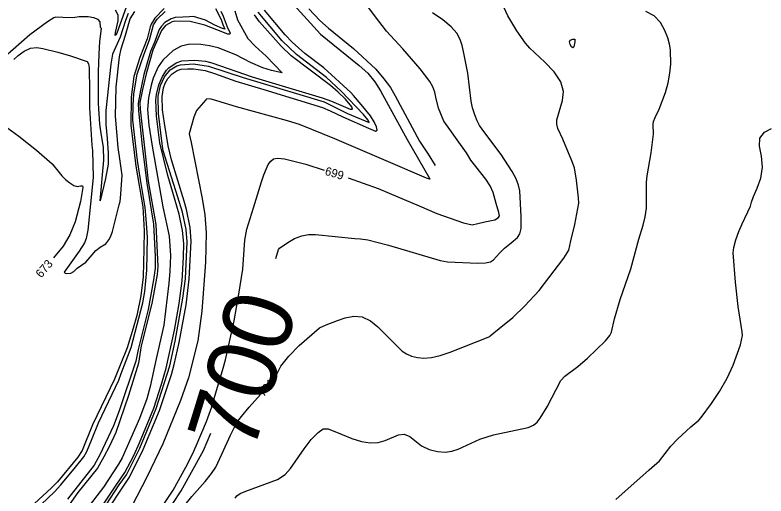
# Model space of a CAD drawing. Extents: x -291892836 to 2945206, y -477993085 to 1832792.
# Drawn here: x 1852014.8 to 1852371.2, y 544783.9 to 545011.9 of the extents above; entities that cross this region are included whole.
import ezdxf

# ---------------------------------------------------------------- set-up
doc = ezdxf.new("R2010")
doc.units = 0
for name, color, linetype in [('DT_X_Contour_Minor', 7, 'Continuous'), ('DT_X_Terrain_Ground_Line', 7, 'Continuous'), ('Level 19', 7, 'Continuous')]:
    doc.layers.add(name, color=color, linetype=linetype)

msp = doc.modelspace()

# ---------------------------------------------------------------- linework, layer by layer
at = {"layer": 'DT_X_Contour_Minor'}
for points in [[(1852214.38, 544973.71), (1852214.04, 544975.4), (1852213.18, 544977.82), (1852211.65, 544980.48), (1852207.06, 544986.4), (1852198.88, 544995.84), (1852191.2, 545004.25), (1852185.5, 545011.67), (1852172, 545029.89), (1852170.75, 545032.2)], [(1852147.09, 545016.73), (1852159.78, 545002.93), (1852178.21, 544988.01), (1852182.22, 544984.33), (1852185.62, 544980.29), (1852188.33, 544975.96), (1852200.96, 544952.88), (1852211.73, 544934.29), (1852211.57, 544934.15), (1852210.07, 544934.63), (1852190.98, 544942.85), (1852166.68, 544953.26), (1852149.87, 544960), (1852144.07, 544961.7), (1852120, 544968.37), (1852110.56, 544971.18), (1852107.98, 544972.05), (1852105.9, 544972.21), (1852105.34, 544971.8), (1852101.02, 544966.62), (1852099.68, 544963.48), (1852097.51, 544955.6), (1852098.34, 544951.54), (1852103.61, 544924.88), (1852104.86, 544917.24), (1852105.54, 544908.68), (1852105.23, 544894.74), (1852103.54, 544871.46), (1852101.51, 544857.41), (1852097.2, 544839.91)], [(1852138.97, 544841.34), (1852140.92, 544845.38), (1852144.72, 544850.23), (1852149.71, 544855.27), (1852159.38, 544863.65), (1852162.54, 544865.12), (1852167.91, 544867.17), (1852171.54, 544868.39), (1852175.56, 544869.15), (1852179.65, 544868.79), (1852183.52, 544866.89), (1852187, 544864.06), (1852198.64, 544852.48), (1852200.62, 544851.22), (1852203, 544850.19), (1852205.77, 544849.49), (1852208.92, 544849.26), (1852212.47, 544849.6), (1852216.54, 544850.53), (1852221.33, 544852.08), (1852240.15, 544859.5), (1852240.35, 544859.86), (1852244.62, 544863.23), (1852251.08, 544868.55), (1852256.86, 544874.12), (1852263.51, 544881.38), (1852275.27, 544896.6), (1852277.62, 544900.39), (1852278.69, 544904.85), (1852280.45, 544912.54), (1852282.4, 544922.67), (1852282.33, 544925.3), (1852281.32, 544933.58), (1852280.33, 544939.46), (1852279.13, 544942.8), (1852274.76, 544953.04), (1852272.37, 544958.13), (1852271.9, 544960.15), (1852272.05, 544962.26), (1852274.73, 544971.36), (1852275.06, 544975.63), (1852273.85, 544980.27), (1852270.64, 544985.05), (1852266.32, 544989.57), (1852259.21, 544996.27), (1852257.06, 544998.66), (1852252.93, 545004.41), (1852248.74, 545011.5), (1852245.08, 545019.58)], [(1852020.98, 544773.99), (1852033.57, 544785.79), (1852036.54, 544789.14), (1852043.52, 544797.62), (1852047.42, 544802.51), (1852048.86, 544805), (1852051.15, 544810.43), (1852054.44, 544818.5), (1852064.02, 544838.79), (1852065.22, 544842.02), (1852069.92, 544854.34), (1852075.54, 544875.49), (1852076.42, 544880.9), (1852077.39, 544891.01), (1852077.66, 544906.44), (1852077.28, 544913.23), (1852076.59, 544920.72), (1852074.29, 544933.94), (1852072.87, 544942.97), (1852070.77, 544962.04), (1852070.83, 544969.26), (1852071.19, 544974.61), (1852072.81, 544983.89), (1852075.93, 544993.01), (1852078.64, 545000.18), (1852080.53, 545007.31), (1852082.26, 545009.92), (1852086, 545013.61)], [(1852112.42, 545013.84), (1852113.55, 545011.34), (1852115.44, 545006.29), (1852116.91, 545003.38), (1852116.73, 545002.84), (1852115.77, 545002.91), (1852110.56, 545004.94), (1852104.92, 545007.19), (1852097.96, 545008.94), (1852090.44, 545008.96), (1852089.47, 545008.75), (1852086.16, 545006.98), (1852084.3, 545004.67), (1852080.25, 544995.24), (1852077.02, 544984.01), (1852075.33, 544976.68), (1852074.08, 544970.43), (1852074.22, 544967.33), (1852077, 544941.86), (1852078.08, 544933.09), (1852081.71, 544912.65), (1852082.67, 544892.63), (1852082.28, 544888.89), (1852079.7, 544875.23), (1852074.68, 544855.01), (1852073.39, 544846.85), (1852068.64, 544831.61), (1852062.71, 544814.04), (1852059.62, 544807.45), (1852056.93, 544802.52), (1852053.99, 544797.13), (1852044.69, 544785.58), (1852037.55, 544775.43)], [(1852049.4, 544909.93), (1852048.54, 544905.97), (1852047.74, 544903.95), (1852045.23, 544899.94), (1852038.19, 544890.05), (1852038.63, 544889.56), (1852039.47, 544889.33), (1852041.38, 544889.57), (1852042.74, 544890.36), (1852044.32, 544891.86), (1852048.35, 544894.79), (1852050.51, 544897.18), (1852053.13, 544900.3), (1852055.17, 544901.81), (1852057.93, 544903.42), (1852059.38, 544905.36), (1852060.26, 544907.06), (1852061.09, 544909.35), (1852064.31, 544921.86), (1852064.78, 544923.46), (1852065.08, 544927.06), (1852065.61, 544935.94), (1852064.68, 544942.59), (1852063.71, 544949.11), (1852062.49, 544963.99), (1852062.81, 544977.73), (1852064.44, 544992.11), (1852065.2, 544995.89), (1852067.29, 545002.32), (1852069.44, 545010.14), (1852071.64, 545013.68)], [(1852109.97, 545014.98), (1852112.59, 545009.84), (1852113.48, 545007.51), (1852114.4, 545005.21), (1852113.3, 545005.47), (1852109.67, 545007.11), (1852105.17, 545009.44), (1852099.57, 545011.28), (1852097.66, 545011.01), (1852094.47, 545010.91), (1852090.82, 545010.76), (1852088.99, 545010.18), (1852085.95, 545008.46), (1852084.28, 545006.64), (1852083.22, 545005.02), (1852082.07, 545002.02), (1852081.13, 544999.4), (1852079.17, 544994.68), (1852075.9, 544983.74), (1852074.3, 544976.17), (1852073.27, 544970.14), (1852073.35, 544966.47), (1852075.12, 544949.73), (1852077.33, 544932.18), (1852080.6, 544912.79), (1852081.34, 544897.45), (1852081.33, 544891.9), (1852080.6, 544886.44), (1852077.95, 544872.33), (1852073.29, 544853.41), (1852072.13, 544847.85), (1852064.23, 544824.25), (1852061.54, 544817.08), (1852055.06, 544803.45), (1852052.35, 544798.48), (1852039.8, 544782.37)], [(1852119.1, 545013.89), (1852120.48, 545009.71), (1852125.25, 545000.87), (1852128.73, 544997.14), (1852134.07, 544992.39), (1852141.6, 544984.47), (1852136.53, 544985.63), (1852132.37, 544986.95), (1852126.52, 544989.49), (1852119.57, 544993.05), (1852111.26, 544996.37), (1852107.11, 544997.4), (1852102.99, 544997.98), (1852097.73, 544998.07), (1852093.62, 544997.2), (1852089.88, 544995.16), (1852084.91, 544990.59), (1852082.82, 544987.35), (1852080.38, 544982.02), (1852079.51, 544978.69), (1852078.16, 544972.61), (1852077.68, 544967.1), (1852078.36, 544959.78), (1852079.85, 544949.79), (1852084.93, 544921.03), (1852087.97, 544907.04), (1852088.53, 544897.94), (1852088.37, 544890.4), (1852087.81, 544884.76), (1852085.46, 544864.93), (1852081.87, 544848.92), (1852079.02, 544835.76), (1852077.36, 544829.92), (1852073.95, 544820.65), (1852065.69, 544802.01), (1852063.87, 544799), (1852056.74, 544788.06), (1852048.44, 544777.17)], [(1852053.89, 544773.45), (1852064.29, 544789.15), (1852067.7, 544793.96), (1852074.03, 544806.57), (1852081.83, 544825.31), (1852088.3, 544845.57), (1852090.89, 544857.31), (1852094.53, 544877.67), (1852095.7, 544886.89), (1852096.59, 544904.39), (1852095.99, 544910.3), (1852094.33, 544918.5), (1852092.09, 544925.64), (1852085.2, 544947.52), (1852084.66, 544950.85), (1852082.99, 544965.26), (1852082.82, 544973.46), (1852083.87, 544978.51), (1852085.81, 544982.62), (1852088.48, 544986), (1852091.58, 544987.84), (1852093.3, 544988.38), (1852099.51, 544988.72), (1852106.63, 544987.75), (1852123.06, 544982.31), (1852148.45, 544974.69), (1852161.56, 544970.71), (1852172.62, 544965.19), (1852182.98, 544961.05), (1852182.48, 544962.15), (1852180.27, 544964.78), (1852169.65, 544975.88), (1852162.7, 544982.36), (1852148.39, 544993.19), (1852141.6, 544999.77), (1852130.21, 545013.29)], [(1852055.73, 544772.58), (1852069.07, 544792.88), (1852075.58, 544805.9), (1852083.38, 544824.45), (1852089.1, 544841.51), (1852090.39, 544846.22), (1852092.75, 544856.72), (1852096.05, 544874.54), (1852097.44, 544886.66), (1852098.37, 544904.76), (1852097.91, 544911.25), (1852096.14, 544919.72), (1852095.06, 544923.67), (1852089.15, 544943.31), (1852087.49, 544949.91), (1852085.79, 544960.65), (1852084.88, 544967.06), (1852084.66, 544973.28), (1852085.32, 544977.45), (1852086.12, 544979.59), (1852087.42, 544981.76), (1852089.36, 544984.08), (1852091.78, 544985.6), (1852093.64, 544986.26), (1852096.86, 544986.49), (1852099.5, 544986.44), (1852105.11, 544985.64), (1852109.52, 544984.25), (1852117.4, 544981.36), (1852119.6, 544980.62), (1852132.86, 544976.67), (1852160.75, 544968.11), (1852164.39, 544966.51), (1852170.38, 544963.6), (1852182.55, 544958.33), (1852185.98, 544956.87), (1852186.66, 544957.27), (1852186.38, 544958.85), (1852185.26, 544961.3), (1852183.5, 544964.15), (1852179.12, 544969.48), (1852175.43, 544973.8), (1852174.23, 544975.21), (1852161.33, 544986.87), (1852152.32, 544993.76), (1852146.3, 544999.07), (1852143.03, 545002.56), (1852133.23, 545014.2)], [(1852067.54, 545015.59), (1852063.2, 545003.32), (1852062.32, 545002.22), (1852062.45, 545003.57), (1852063.76, 545009.18), (1852063.8, 545011.82), (1852062.47, 545014.25)], [(1852085.62, 545015.07), (1852081.13, 545010.46), (1852079.39, 545007.62), (1852079, 545006.26), (1852077.59, 545000.66), (1852074.09, 544991.87), (1852071.2, 544982.76), (1852069.87, 544972.93), (1852069.76, 544959.77), (1852072.09, 544940.32), (1852075.4, 544921.04), (1852076.17, 544909.64), (1852076.03, 544901.13)], [(1852138.67, 544896.46), (1852139.82, 544900.74), (1852140.41, 544901.38), (1852144.3, 544904.14), (1852147.49, 544905.91), (1852150.89, 544907.31), (1852154.13, 544907.93), (1852157.39, 544907.9), (1852176.02, 544905.92), (1852178.83, 544905.84), (1852182.32, 544905.38), (1852192.02, 544902.88), (1852216.67, 544895.57), (1852220.14, 544894.93), (1852234.51, 544894.29), (1852238.04, 544894.41), (1852240.45, 544894.96), (1852241.95, 544895.85), (1852244.69, 544899.03), (1852247.09, 544901.47), (1852250.29, 544903.98), (1852253.38, 544906.38), (1852254.45, 544908.19), (1852254.99, 544910.74), (1852255.06, 544916.43), (1852254.37, 544928.6), (1852253.74, 544931.21), (1852252.6, 544934.22), (1852250.81, 544937.72), (1852245.5, 544945.81), (1852237.76, 544956.03), (1852235.31, 544959.54), (1852234.14, 544961.81), (1852232.99, 544964.66), (1852231.98, 544967.86), (1852231.26, 544971.12), (1852229.7, 544984.29), (1852227.61, 544994.7), (1852227.07, 544997.53), (1852226.13, 545000.32), (1852224.45, 545003.28), (1852221.78, 545006.41), (1852217.94, 545009.66), (1852212.95, 545012.91)], [(1852154.32, 545014.87), (1852159.49, 545009.38), (1852163.6, 545005.69), (1852175.41, 544996.08), (1852186.05, 544986.29), (1852189.91, 544981.71), (1852193.02, 544977.57), (1852195.22, 544973.69), (1852206.81, 544952.11), (1852210.93, 544945.93), (1852214.26, 544940.59)], [(1852314.6, 544932.69), (1852314.9, 544935.7), (1852316.81, 544946.58), (1852317.79, 544955.5), (1852317.74, 544960.05), (1852317.89, 544961.44), (1852318.72, 544963.29), (1852320.6, 544967.24), (1852323.57, 544975.13), (1852324.86, 544979.82), (1852325.67, 544984.44), (1852326.05, 544988.7), (1852325.95, 544995.41), (1852325.5, 544998.15), (1852324.66, 545001.13), (1852323.31, 545004.66), (1852321.24, 545008.33), (1852318.22, 545011.48), (1852314.18, 545013.62)], [(1852057.88, 544966.66), (1852057.84, 544960.09), (1852058.47, 544953.45), (1852059, 544946.39), (1852059, 544941.25), (1852057.73, 544934.5), (1852055.16, 544923.78), (1852056.96, 544943.05), (1852056.78, 544949.24), (1852055.67, 544955.83), (1852055.12, 544960.22), (1852054.47, 544969.98), (1852054.46, 544985.07), (1852054.77, 544993.36), (1852055.07, 544999.33), (1852055.8, 545005.53), (1852055.39, 545006.05), (1852055.24, 545008.73), (1852054.25, 545009.78), (1852052.15, 545010.57), (1852049.48, 545011.05), (1852045.23, 545011.1), (1852042.21, 545010.65), (1852037.52, 545010.76), (1852034.15, 545010.93), (1852033.23, 545010.68), (1852030.27, 545008.74), (1852021.9, 545002.57), (1852001.84, 544985.23)], [(1852055.79, 544778.67), (1852062.79, 544789.05), (1852066.95, 544794.96), (1852071.17, 544803.13), (1852073.88, 544809.04), (1852080.74, 544825.58), (1852084.37, 544836.95), (1852086.63, 544844.48), (1852090.51, 544862.48), (1852092.74, 544875.13), (1852094.07, 544885.9), (1852094.76, 544897.06), (1852094.94, 544903.57), (1852094.36, 544909.76), (1852092.76, 544917.52), (1852090.54, 544925.12), (1852087.34, 544935.91), (1852083.53, 544951.38), (1852082.01, 544964), (1852081.71, 544971.71), (1852082.04, 544974.28), (1852083.08, 544978.87), (1852084.75, 544982.81), (1852086.7, 544985.71), (1852087.79, 544986.95), (1852091.3, 544989.34), (1852093.92, 544990.15), (1852100.13, 544990.59), (1852105.25, 544989.98), (1852108.27, 544989.21), (1852127.3, 544982.62), (1852146.39, 544976.98), (1852160.67, 544972.71), (1852164.97, 544971.15), (1852173.96, 544967.27), (1852175.04, 544967.34), (1852174.75, 544968.36), (1852171.67, 544971.96), (1852168.19, 544975.4), (1852164.5, 544978.46), (1852145.88, 544992.59), (1852141.07, 544997.22), (1852130.85, 545008.71), (1852128.53, 545011.99)], [(1852068.48, 545012.58), (1852067.28, 545009.26), (1852064.77, 545001.4), (1852061.01, 544993.45), (1852060.28, 544988.65), (1852057.88, 544966.66)], [(1852280.49, 545000.48), (1852280.46, 544999.17), (1852280.07, 544996.88), (1852279.61, 544996.37), (1852278.95, 544996.88), (1852278.33, 544998.01), (1852278.05, 544999.19), (1852278.33, 544999.95), (1852279.6, 545000.47), (1852280.49, 545000.48)], [(1852014.18, 544990.81), (1852016.35, 544992.72), (1852019.11, 544994.77), (1852022.14, 544996.21), (1852025.16, 544996.52), (1852028.02, 544996.05), (1852035.09, 544994.25), (1852041.08, 544992.62), (1852049, 544989.84), (1852049.76, 544988.83), (1852050.01, 544986.84), (1852050.11, 544975.76), (1852050.24, 544967.86), (1852051.29, 544950.26), (1852051.57, 544947.64), (1852051.84, 544934.86), (1852049.4, 544909.93)], [(1852221.13, 544957.73), (1852218.28, 544961.68), (1852215.87, 544967.72), (1852214.52, 544973.03), (1852214.38, 544973.71)], [(1852009.7, 544959.5), (1852016.68, 544954.46), (1852025.02, 544947.86), (1852032.46, 544941.33), (1852035.78, 544937.26), (1852037.04, 544935.64), (1852038.81, 544933.91), (1852040.87, 544932.3), (1852042.8, 544931.15), (1852044.25, 544930.68), (1852045.95, 544930.91), (1852046.87, 544930.94), (1852046.98, 544930.17), (1852045.89, 544923.45), (1852043.39, 544913.95), (1852040.87, 544907.77), (1852037.73, 544902.36), (1852033.02, 544896.85)], [(1852206.59, 544921.44), (1852215.04, 544917.84), (1852227.6, 544913.46), (1852231.77, 544912.5), (1852234.54, 544913.08), (1852237.86, 544913.91), (1852242.54, 544914.76), (1852244.33, 544916), (1852244.69, 544916.71), (1852244.48, 544918.36), (1852243.14, 544922.53), (1852241.81, 544927.74), (1852240.4, 544930.88), (1852238.2, 544934.15), (1852231.15, 544943.08), (1852229.14, 544946.59), (1852224.73, 544952.73), (1852221.13, 544957.73)], [(1852299.94, 544782.28), (1852315.86, 544796.37), (1852320.66, 544800.51), (1852326.12, 544807.44), (1852329.18, 544810.83), (1852335.57, 544816.64), (1852339.39, 544819.79), (1852340.54, 544821.08), (1852345.41, 544827.79), (1852349.19, 544833.47), (1852352.87, 544839.75), (1852355.74, 544845.91), (1852359.09, 544855.51), (1852360.17, 544859.92), (1852359.94, 544861.72), (1852358.04, 544873.74), (1852356.81, 544885.22), (1852355.64, 544899.2), (1852355.94, 544901.78), (1852356.88, 544905.29), (1852358.28, 544909.27), (1852359.86, 544912.98), (1852363.95, 544921.26), (1852364.39, 544923.14), (1852365.31, 544925.87), (1852367, 544929.81), (1852368.74, 544934.64), (1852369.63, 544939.86), (1852369.1, 544945.01), (1852368.2, 544949.7), (1852368.35, 544953.56), (1852370.51, 544956.34), (1852373.8, 544958.15)], [(1852131.83, 544932.88), (1852132.83, 544936.1), (1852135.02, 544941.13), (1852136.16, 544942.71), (1852137.5, 544943.69), (1852139.51, 544944.03), (1852142.76, 544943.67), (1852152.82, 544941.23), (1852161.48, 544938.44)], [(1852172.89, 544934.7), (1852187.15, 544929.68), (1852192.39, 544927.5), (1852206.59, 544921.44)], [(1852113.59, 544844.49), (1852114.76, 544848.48), (1852118.79, 544867), (1852121.1, 544879.62), (1852122.99, 544891.47), (1852123.84, 544905.14), (1852124.85, 544910.43), (1852127.95, 544920.48), (1852131.83, 544932.88)], [(1852119.34, 544782.9), (1852120.16, 544783.94), (1852121.74, 544785.06), (1852124.32, 544786.2), (1852139.37, 544791.74), (1852143.01, 544794.14), (1852145.55, 544797), (1852152.03, 544806.22), (1852155.45, 544810.6), (1852158.62, 544814.06), (1852161.11, 544815.71), (1852163.4, 544815.77), (1852170.09, 544813.02), (1852174.61, 544811.2), (1852179.19, 544809.76), (1852183.36, 544809.11), (1852187.1, 544809.28), (1852190.54, 544810.19), (1852196.81, 544812.93), (1852199.59, 544813.27), (1852202.15, 544812.1), (1852207.8, 544807.71), (1852211.42, 544805.99), (1852215.31, 544804.98), (1852219, 544804.7), (1852222.16, 544805.15), (1852225.09, 544806.17), (1852235.48, 544810.76), (1852241.86, 544812.87), (1852258.38, 544816.29), (1852260.82, 544817.46), (1852262.59, 544818.94), (1852264.11, 544820.86), (1852267.37, 544826.23), (1852273.81, 544838.7), (1852275.8, 544840.71), (1852281.92, 544845.35), (1852286.49, 544849.28), (1852295.05, 544857.52), (1852297.14, 544860), (1852297.97, 544861.63), (1852299.36, 544867.89), (1852302.1, 544877.04), (1852307.07, 544891.54), (1852310.83, 544905.61), (1852312.99, 544912.29), (1852313.92, 544916.18), (1852314.52, 544920.36), (1852314.6, 544928.97), (1852314.6, 544932.69)], [(1852211.73, 544934.29), (1852211.86, 544934.25)], [(1852076.03, 544901.13), (1852075.6, 544887.77), (1852074.54, 544878.81), (1852072.63, 544869.48), (1852070.94, 544863.53), (1852068.04, 544854.08), (1852061.97, 544839.25), (1852051.63, 544817.7), (1852046.71, 544805.39), (1852044.7, 544802.33), (1852034.9, 544790.6), (1852032.02, 544787.65), (1852018.06, 544774.81)], [(1852108.43, 544826.89), (1852113.59, 544844.49)], [(1852097.2, 544839.91), (1852093.41, 544829.21), (1852084.9, 544808.55), (1852077.4, 544792.74), (1852067.84, 544774.49), (1852056.8, 544759.2), (1852048.92, 544750.6), (1852039.02, 544740.57), (1852036.37, 544735.42), (1852035.25, 544732), (1852033.87, 544722.07), (1852033.61, 544711.61), (1852034.3, 544699.24), (1852035.87, 544692.73), (1852043.32, 544668.56), (1852044.51, 544659.38), (1852044.94, 544652.06), (1852044.06, 544640.16), (1852040.91, 544620.13), (1852037.33, 544612.8), (1852035.8, 544610.14)], [(1852091.71, 544773.62), (1852095.49, 544779.58), (1852098.78, 544783.58), (1852105.14, 544790.76), (1852108.14, 544794.49), (1852110.13, 544797.53), (1852112.95, 544803.76), (1852117.01, 544812.71), (1852120.07, 544818.71), (1852122.37, 544821.64), (1852125.99, 544825.96), (1852131.35, 544832.06)], [(1852100.72, 544807.7), (1852105.68, 544819.2), (1852108.23, 544826.19), (1852108.43, 544826.89)], [(1852089.71, 544780.31), (1852093.73, 544786.29), (1852104.2, 544805.53), (1852107.79, 544813.73)], [(1852070.47, 544701.97), (1852066.84, 544706.96), (1852062.62, 544710.57), (1852060.59, 544712.25), (1852058.9, 544713.99), (1852057.6, 544715.74), (1852056.68, 544717.44), (1852055.82, 544720.58), (1852055.62, 544725.44), (1852055.74, 544730.37), (1852056.01, 544733.37), (1852056.62, 544736.29), (1852057.63, 544738.84), (1852061.16, 544744.69), (1852063.17, 544747.64), (1852067.72, 544753.44), (1852072.19, 544758.99), (1852080.82, 544773.16), (1852089.82, 544786.6), (1852095.9, 544797.53), (1852099, 544803.72), (1852100.72, 544807.7)]]:
    msp.add_lwpolyline(points, dxfattribs=at)

# ---------------------------------------------------------------- texts
at = {"layer": 'DT_X_Terrain_Ground_Line'}
msp.add_text('700', height=33, rotation=72.8229, dxfattribs=at).set_placement((1852127.59, 544803.51))
at = {"layer": 'Level 19'}
for s, rotation, p in [('699', 343.5627, (1852161.6, 544936.24)), ('673', 49.4634, (1852027.24, 544887.02)), ('701', 48.7014, (1852132.76, 544830.63))]:
    msp.add_text(s, height=4, rotation=rotation, dxfattribs=at).set_placement(p)

doc.saveas('drawing.dxf')
